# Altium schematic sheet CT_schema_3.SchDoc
size 365 x 192 mm
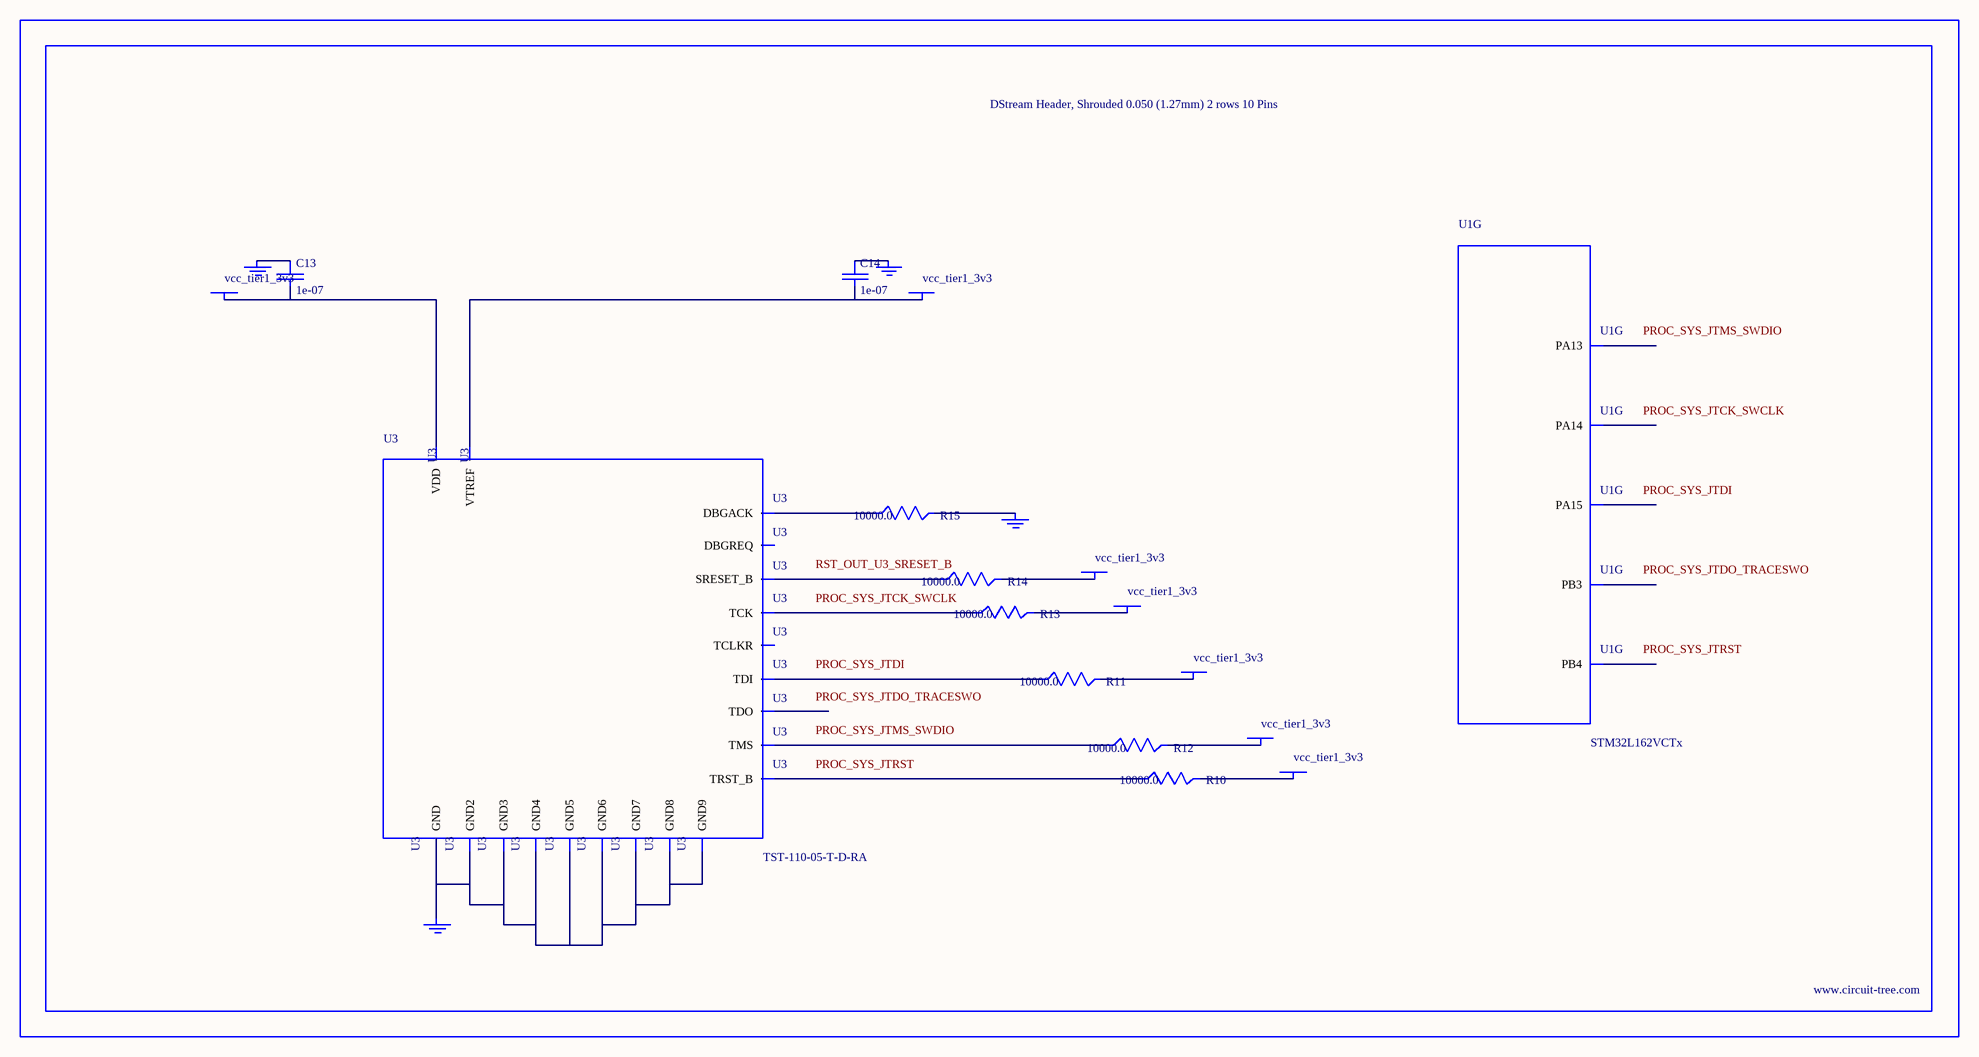
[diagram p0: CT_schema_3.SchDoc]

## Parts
BORDER2  (no value)
C13  1e-07  [C0402]
C14  1e-07  [C0402]
GND_INSTANCE_2_0  (no value)
GND_INSTANCE_2_1  (no value)
GND_INSTANCE_2_2  (no value)
GND_INSTANCE_2_3  (no value)
POWER_INSTANCE_2_0  vcc_tier1_3v3
POWER_INSTANCE_2_1  vcc_tier1_3v3
POWER_INSTANCE_2_2  vcc_tier1_3v3
POWER_INSTANCE_2_3  vcc_tier1_3v3
POWER_INSTANCE_2_4  vcc_tier1_3v3
POWER_INSTANCE_2_5  vcc_tier1_3v3
POWER_INSTANCE_2_6  vcc_tier1_3v3
R10  10000.0  [R0603]
R11  10000.0  [R0603]
R12  10000.0  [R0603]
R13  10000.0  [R0603]
R14  10000.0  [R0603]
R15  10000.0  [R0603]
U1  STM32L162VCTx  [LQFP100]  (part G of 11)
U3  TST-110-05-T-D-RA  [TST-110-05-T-D-RA]

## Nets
NetC13_1: C13.1 GND_INSTANCE_2_1.0(GND)
NetC13_2: C13.2 POWER_INSTANCE_2_1.0(PWR) U3.2(VDD)
NetC14_1: C14.1 GND_INSTANCE_2_0.0(GND)
NetC14_2: C14.2 POWER_INSTANCE_2_0.0(PWR) U3.1(VTREF)
NetGND_INSTANCE_2_2_0: GND_INSTANCE_2_2.0(GND) R15.2
NetGND_INSTANCE_2_3_0: GND_INSTANCE_2_3.0(GND) U3.4(GND) U3.6(GND2) U3.8(GND3) U3.10(GND4) U3.12(GND5) U3.14(GND6) U3.16(GND7) U3.18(GND8) U3.20(GND9)
NetPOWER_INSTANCE_2_2_0: POWER_INSTANCE_2_2.0(PWR) R10.2
NetPOWER_INSTANCE_2_3_0: POWER_INSTANCE_2_3.0(PWR) R11.2
NetPOWER_INSTANCE_2_4_0: POWER_INSTANCE_2_4.0(PWR) R12.2
NetPOWER_INSTANCE_2_5_0: POWER_INSTANCE_2_5.0(PWR) R13.2
NetPOWER_INSTANCE_2_6_0: POWER_INSTANCE_2_6.0(PWR) R14.2
NetR10_1: R10.1 U3.3(TRST_B)
NetR11_1: R11.1 U3.5(TDI)
NetR12_1: R12.1 U3.7(TMS)
NetR13_1: R13.1 U3.9(TCK)
NetR14_1: R14.1 U3.15(SRESET_B)
NetR15_1: R15.1 U3.19(DBGACK)

Not connected (* = marked no-connect by the designer): U1 72(PA13) 76(PA14) 77(PA15) 89(PB3) 90(PB4); U3 11(TCLKR) 13(TDO) 17(DBGREQ)

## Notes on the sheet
- Labels drawn without touching a wire or pin: PROC_SYS_JTCK_SWCLK, PROC_SYS_JTDI, PROC_SYS_JTDO_TRACESWO, PROC_SYS_JTMS_SWDIO, PROC_SYS_JTRST, RST_OUT_U3_SRESET_B

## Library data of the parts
BORDER2 = BORDER_PAGE2
C13 C14 = C0402C104K3RACTU
GND_INSTANCE_2_0-GND_INSTANCE_2_3 = GND
POWER_INSTANCE_2_0-POWER_INSTANCE_2_6 = PWR
R10-R15 = RC0603JR-0710KL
